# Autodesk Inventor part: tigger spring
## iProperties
Created: 2006-04
Part Number: tigger spring
Document SubType Name: Modeling
Designer: Калинин
Author: Калинин
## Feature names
1. Пружина1
2. Вращение1 [Revolution]
3. Выдавливание1 [Extrusion]
4. Сдвиг1
5. Вращение2 [Revolution]
6. Выдавливание2 [Extrusion]
7. Сдвиг2
